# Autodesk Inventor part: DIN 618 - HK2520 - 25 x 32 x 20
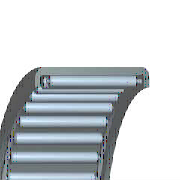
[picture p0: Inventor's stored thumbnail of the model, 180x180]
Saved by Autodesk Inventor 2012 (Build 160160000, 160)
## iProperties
Created: 2011-02
Part Number: DIN 618 - HK2520 - 25 x 32 x 20
Material: Steel, Mild
Description: Needle Roller Bearing Drawn Cup
Document SubType Name: Modeling
Standard: DIN 618
Designer: Admin
Standards Organization: DIN
Language: en-US
Size Designation: HK2520 - 25 x 32 x 20
Categories: <MemberInstance><Categories><Category DisplayName="Shaft Parts" InternalName="7f7aeb1f-a693-4053-b835-cee3144e0d98" Mnemonic="SHFT"><Category DisplayName="Beari
Density: 1 g/cm^3
IsCustomPart: 0
Author: Admin
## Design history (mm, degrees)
revolve "Body" stored, may be unused: angle "d43" = 90 deg
revolve "Groove" stored, may be unused: angle "d44" = 90 deg
revolve "Roller" stored, may be unused: angle "d48" = 90 deg
pattern_circular "Grooves" dims angle "d4" = 360 deg
body "Solid1"
sketch "Sketch"
  geometry: L1 (10, 13.812)-(10, 13.375); L2 (0.875, 15.125)-(0.875, 12.5); L3 (0.875, 12.5)-(0, 12.5); L4 (0, 16)-(20, 16); L5 (1.531, 14.25)-(1.531, 13.375); L6 (19.125, 15.125)-(19.125, 12.5); L7 (19.125, 12.5)-(20, 12.5); L8 (20, 12.5)-(20, 16); L9 (18.469, 14.25)-(18.469, 13.375); L10 (0.875, 15.125)-(19.125, 15.125); L11 (2.713, 13.812)-(2.713, 15.388); L12 (17.287, 15.388)-(17.288, 13.813); L13 (2.713, 15.388)-(17.287, 15.388); L14 (1.531, 14.25)-(18.469, 14.25); L15 (1.531, 13.375)-(18.469, 13.375); L16 (1.531, 13.812)-(18.469, 13.813); L17 (3.527, 12.5)-(16.473, 12.5); L18 (-2.4, 0)-(14.4, 0) reference; L19 (0, -0.154)-(0, 4.109) reference; A1 r 1.838 centre (4.813, 13.812) between (3.527, 15.125) and (2.975, 13.812); A2 r 1.838 centre (15.188, 13.813) between (17.025, 13.813) and (16.473, 15.125); A3 r 1.838 centre (4.813, 13.812) between (2.975, 13.812) and (3.527, 12.5); A4 r 1.838 centre (15.188, 13.813) between (16.473, 12.5) and (17.025, 13.813)
  constraints: 34 end point, 9 point on line, 8 point on circle, 5 symmetric about line, 4 centre point, 4 midpoint, 2 collinear, 1 parallel, 1 perpendicular, 7 other
  dimensions: "d0" = 1.8375 radius of A3 (= -0.7 x YM - 0.35 x WD + 0.35 x BD); "d8" = 25 diameter of L17 L18 (= WD); "d9" = 30.25 diameter of L10 L18 (= BD - 2 x YM); "d10" = 32 diameter of L4 L18 (= BD); "d11" = 28.5 diameter of L14 L18 (= -1.33333 x YM + 0.666667 x BD + 0.333333 x WD); "d12" = 30.775 diameter of L13 L18 (= -2.2 x YM + 1.1 x BD - 0.1 x WD); "d13" = 0.875 distance between parallel lines of L19 L2 (= YM); "d14" = 2.7125 distance between parallel lines of L19 L11 (= 0.35 x BD - 0.35 x WD + 0.3 x YM); "d15" = 1.53125 distance between parallel lines of L19 L5 (= 0.75 x YM + 0.125 x BD - 0.125 x WD); "d16" = 4.8125 distance from line of A1.centre L19 (= -0.5 x YM - 0.75 x WD + 0.75 x BD); "d17" = 20 distance between parallel lines of L19 L8 (= KB); "d18" = 10 distance from line of L19 L1.start (= 0.5 x KB)
fillet "Fillet1" dims "d1" = 0.65625 (= -0.25 x YM - 0.125 x WD + 0.125 x BD), "d2" = 1.53125 (= 0.125 x BD - 0.125 x WD + 0.75 x YM)
other parameters: "WD" = 25 [user parameter; used in 11 equation terms], "BD" = 32 [user parameter; used in 12 equation terms], "KB" = 20 [user parameter; used in 2 equation terms], "YM" = 0.875 [user parameter; used in 11 equation terms], "d5" = 0, "d6" = 0, "d7" = 0, "d69" = 0, "d70" = 0, "BC0" = 3.4e+07 [user parameter], "BBA" = 0 [user parameter], "KRS" = 0.8 [user parameter], "BC" = 1.96e+07 [user parameter], "BR" = 16 (= 0.5 x BD) [user parameter], "WR" = 12.5 (= 0.5 x WD) [user parameter]
